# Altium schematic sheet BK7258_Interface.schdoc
size 326 x 187 mm
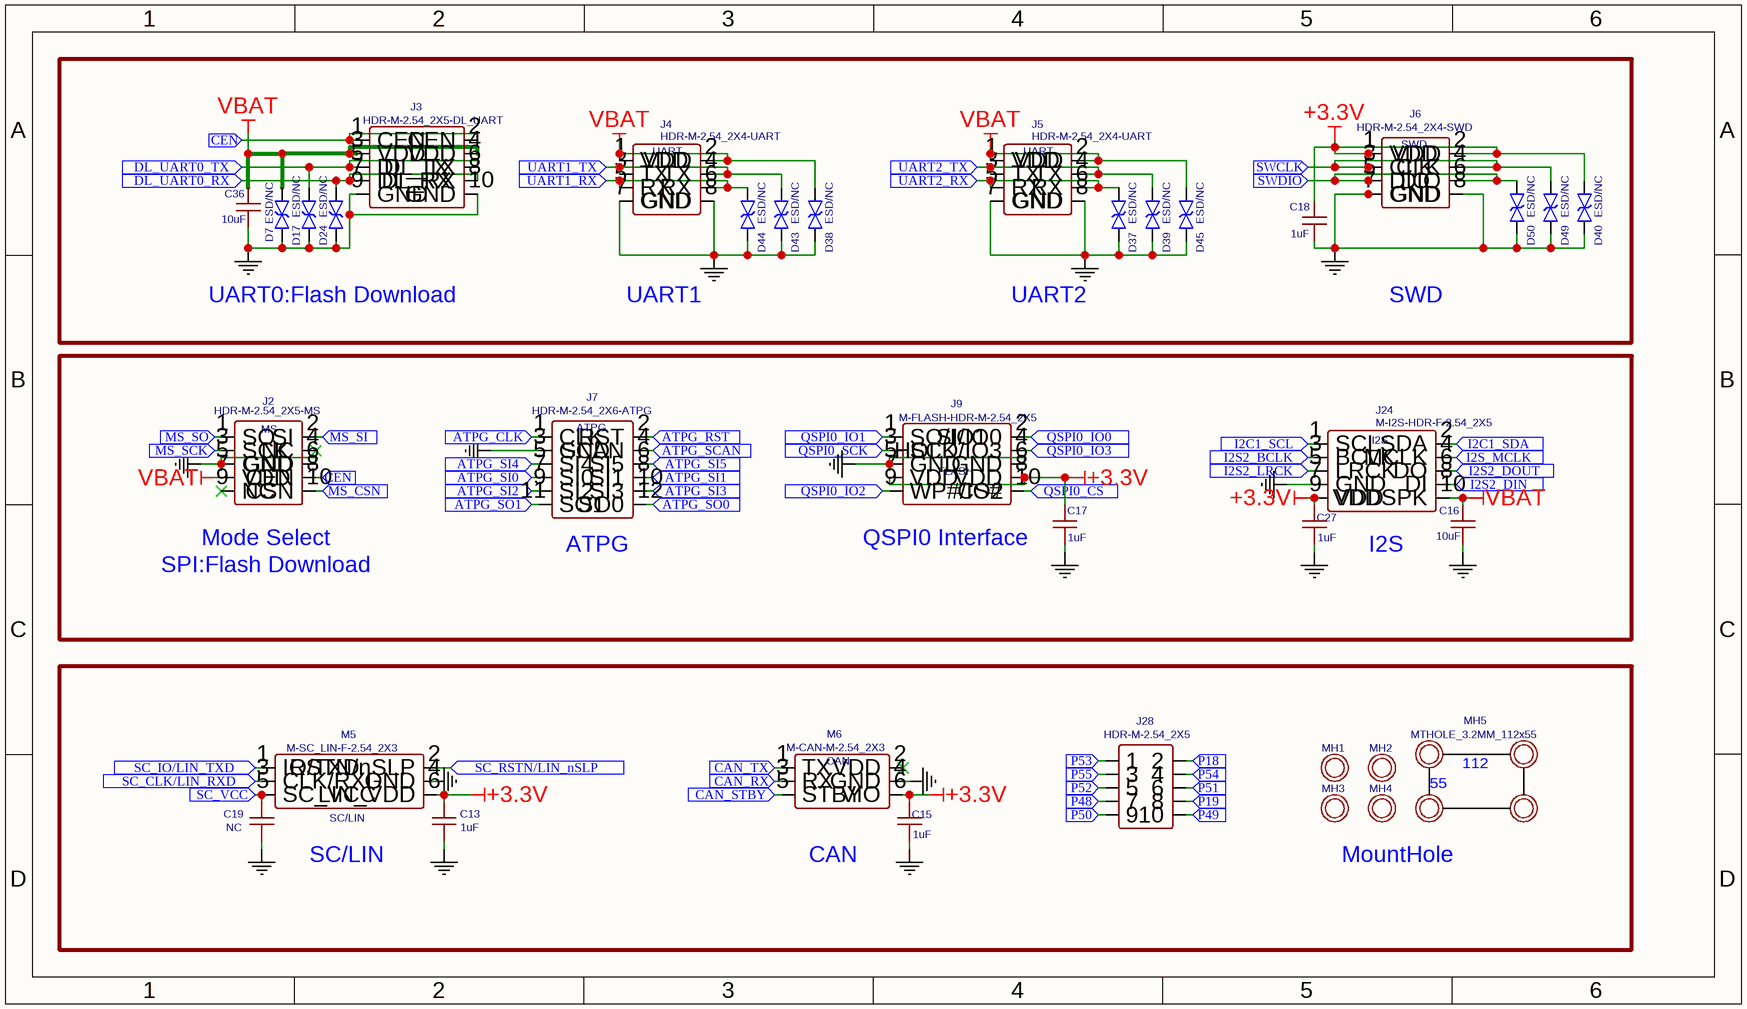
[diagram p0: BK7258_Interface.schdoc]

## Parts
C13  1uF  [C0402]
C15  1uF  [C0402]
C16  10uF  [C0603]
C17  1uF  [C0402]
C18  1uF  [C0402]
C19  NC  [C0402]
C27  1uF  [C0402]
C36  10uF  [C0603]
D7  ESD/NC  [ESD0402]
D17  ESD/NC  [ESD0402]
D24  ESD/NC  [ESD0402]
D37  ESD/NC  [ESD0402]
D38  ESD/NC  [ESD0402]
D39  ESD/NC  [ESD0402]
D40  ESD/NC  [ESD0402]
D43  ESD/NC  [ESD0402]
D44  ESD/NC  [ESD0402]
D45  ESD/NC  [ESD0402]
D49  ESD/NC  [ESD0402]
D50  ESD/NC  [ESD0402]
J2  HDR-M-2.54_2X5-MS  [JH2X5_FLASH]
J3  HDR-M-2.54_2X5-DL_UART  [HDR-M-2.54_2X5-DL_UART]
J4  HDR-M-2.54_2X4-UART  [HDR-M-2.54_2X4-UART]
J5  HDR-M-2.54_2X4-UART  [HDR-M-2.54_2X4-UART]
J6  HDR-M-2.54_2X4-SWD  [HDR-M-2.54_2X4-SWD]
J7  HDR-M-2.54_2X6-ATPG  [JH2X6]
J9  M-FLASH-HDR-M-2.54_2X5  [JH2X5_FLASH]
J24  M-I2S-HDR-F-2.54_2X5  [M-I2S-HDR-F-2.54_2X5]
J28  HDR-M-2.54_2X5  [HDR-M-2.54_2X5]
M5  M-SC_LIN-F-2.54_2X3  [M-SC_LIN-F-2.54_2X3]
M6  M-CAN-M-2.54_2X3  [M-CAN-M-2.54_2X3]
MH1  MTHOLE_3.2MM  [MTHOLE_3.2MM]  (value not drawn)
MH2  MTHOLE_3.2MM  [MTHOLE_3.2MM]  (value not drawn)
MH3  MTHOLE_3.2MM  [MTHOLE_3.2MM]  (value not drawn)
MH4  MTHOLE_3.2MM  [MTHOLE_3.2MM]  (value not drawn)
MH5  MTHOLE_3.2MM_112x55  [MTHOLE_3.2MM_112X55]

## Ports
ATPG_CLK (in), ATPG_RST (in), ATPG_SCAN (in), ATPG_SI0 (in), ATPG_SI1 (in), ATPG_SI2 (in), ATPG_SI3 (in), ATPG_SI4 (in), ATPG_SI5 (in), ATPG_SO0 (in), ATPG_SO1 (in), CAN_RX (in), CAN_STBY (in), CAN_TX (in), CEN (in), DL_UART0_RX (in), DL_UART0_TX (in), I2C1_SCL (in), I2C1_SDA (in), I2S2_BCLK (in), I2S2_DIN (in), I2S2_DOUT (in), I2S2_LRCK (in), I2S_MCLK (in), MS_CSN (in), MS_SCK (in), MS_SI (in), MS_SO (in), P18 (in), P19 (in), P48 (in), P49 (in), P50 (in), P51 (in), P52 (in), P53 (in), P54 (in), P55 (in), QSPI0_CS (in), QSPI0_IO0 (in), QSPI0_IO1 (in), QSPI0_IO2 (in), QSPI0_IO3 (in), QSPI0_SCK (in), SC_CLK/LIN_RXD (in), SC_IO/LIN_TXD (in), SC_RSTN/LIN_nSLP (in), SC_VCC (in), SWCLK (in), SWDIO (in), UART1_RX (in), UART1_TX (in), UART2_RX (in), UART2_TX (in)

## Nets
+3.3V: C13.1 C15.1 C17.1 C18.1 C27.1 D40.1 J6.1(VDD) J6.2(VDD) J9.7(VDD) J9.8(VDD) J24.9(VDD) M5.6(LIN_VDD) M6.6(VIO)
GGND: C13.2 C15.2 C16.2 C17.2 C18.2 C19.2 C27.2 C36.2 D7.2 D17.2 D24.2 D37.2 D38.2 D39.2 D40.2 D43.2 D44.2 D45.2 D49.2 D50.2 J2.5(GND) J2.6(GND) J3.9(GND) J3.10(GND) J4.7(GND) J4.8(GND) J5.7(GND) J5.8(GND) J6.7(GND) J6.8(GND) J7.3(GND) J9.5(GND) J9.6(GND) J24.7(GND) M5.4(GND) M6.4(GND)
VBAT: C16.1 C36.1 D7.1 D38.1 D45.1 J2.7(VDD) J3.3(VDD) J3.4(VDD) J4.1(VDD) J4.2(VDD) J5.1(VDD) J5.2(VDD) J24.10(VDDSPK)
ATPG_CLK: J7.1(CLK) ; port ATPG_CLK
ATPG_RST: J7.2(RST) ; port ATPG_RST
ATPG_SCAN: J7.4(SCAN) ; port ATPG_SCAN
ATPG_SI0: J7.7(SI0) ; port ATPG_SI0
ATPG_SI1: J7.8(SI1) ; port ATPG_SI1
ATPG_SI2: J7.9(SI2) ; port ATPG_SI2
ATPG_SI3: J7.10(SI3) ; port ATPG_SI3
ATPG_SI4: J7.5(SI4) ; port ATPG_SI4
ATPG_SI5: J7.6(SI5) ; port ATPG_SI5
ATPG_SO0: J7.12(SO0) ; port ATPG_SO0
ATPG_SO1: J7.11(SO1) ; port ATPG_SO1
CAN_RX: M6.3(RX) ; port CAN_RX
CAN_STBY: M6.5(STBY) ; port CAN_STBY
CAN_TX: M6.1(TX) ; port CAN_TX
CEN: J2.8(CEN) J3.1(CEN) J3.2(CEN) ; port CEN
DL_UART0_RX: D24.1 J3.7(DL_RX) J3.8(DL_RX) ; port DL_UART0_RX
DL_UART0_TX: D17.1 J3.5(DL_TX) J3.6(DL_TX) ; port DL_UART0_TX
I2C1_SCL: J24.1(SCL) ; port I2C1_SCL
I2C1_SDA: J24.2(SDA) ; port I2C1_SDA
I2S2_BCLK: J24.3(BCLK) ; port I2S2_BCLK
I2S2_DIN: J24.8(DI) ; port I2S2_DIN
I2S2_DOUT: J24.6(DO) ; port I2S2_DOUT
I2S2_LRCK: J24.5(LRCK) ; port I2S2_LRCK
I2S_MCLK: J24.4(MCLK) ; port I2S_MCLK
MS_CSN: J2.10(CSN) ; port MS_CSN
MS_SCK: J2.3(SCK) ; port MS_SCK
MS_SI: J2.2(SI) ; port MS_SI
MS_SO: J2.1(SO) ; port MS_SO
P18: J28.2 ; port P18
P19: J28.8 ; port P19
P48: J28.7 ; port P48
P49: J28.10 ; port P49
P50: J28.9 ; port P50
P51: J28.6 ; port P51
P52: J28.5 ; port P52
P53: J28.1 ; port P53
P54: J28.4 ; port P54
P55: J28.3 ; port P55
QSPI0_CS: J9.10(CS#) ; port QSPI0_CS
QSPI0_IO0: J9.2(SI/IO0) ; port QSPI0_IO0
QSPI0_IO1: J9.1(SO/IO1) ; port QSPI0_IO1
QSPI0_IO2: J9.9(WP#/IO2) ; port QSPI0_IO2
QSPI0_IO3: J9.4(HOLD/IO3) ; port QSPI0_IO3
QSPI0_SCK: J9.3(SCK) ; port QSPI0_SCK
SC_CLK/LIN_RXD: M5.3(CLK/RXD) ; port SC_CLK/LIN_RXD
SC_IO/LIN_TXD: M5.1(IO/TXD) ; port SC_IO/LIN_TXD
SC_RSTN/LIN_nSLP: M5.2(RSTN/nSLP) ; port SC_RSTN/LIN_nSLP
SC_VCC: C19.1 M5.5(SC_VCC) ; port SC_VCC
SWCLK: D49.1 J6.3(CLK) J6.4(CLK) ; port SWCLK
SWDIO: D50.1 J6.5(DIO) J6.6(DIO) ; port SWDIO
UART1_RX: D44.1 J4.5(RX) J4.6(RX) ; port UART1_RX
UART1_TX: D43.1 J4.3(TX) J4.4(TX) ; port UART1_TX
UART2_RX: D37.1 J5.5(RX) J5.6(RX) ; port UART2_RX
UART2_TX: D39.1 J5.3(TX) J5.4(TX) ; port UART2_TX

Not connected (* = marked no-connect by the designer): J2 4(NC)* 9(NC)*; M6 2(VDD)*

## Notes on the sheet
- UART0:Flash Download
- UART1
- UART2
- SWD
- (near J2) Mode Select
- (near J7) ATPG
- QSPI0 Interface
- I2S
- SPI:Flash Download
- SC/LIN
- CAN
- MountHole

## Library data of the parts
C13 C15 C17 C18 C27 = 1uF: Manufacturer Part Number: 08055A390JATMA; Manufacturer: AVX; APN: C012-0
C16 C36 = 10uF: Manufacturer Part Number: 06035A101KAT2A; Manufacturer: AVX; APN: C029-0
C19 = NC: Manufacturer Part Number: 08055A390JATMA; Manufacturer: AVX; APN: C012-0
D7 D17 D24 D37-D40 D43-D45 D49 D50 = ESD/NC: Contributor: D-MAN
J2 = HDR-M-2.54_2X5-MS: Contributor: qunshan.xu
J3 = HDR-M-2.54_2X5-DL_UART: Contributor: qunshan.xu
J4 J5 = HDR-M-2.54_2X4-UART: Contributor: qunshan.xu
J6 = HDR-M-2.54_2X4-SWD: Contributor: qunshan.xu
J7 = HDR-M-2.54_2X6-ATPG: Contributor: qunshan.xu
J9 = M-FLASH-HDR-M-2.54_2X5: Contributor: qunshan.xu
J24 = M-I2S-HDR-F-2.54_2X5: Contributor: qunshan.xu
J28 = HDR-M-2.54_2X5: Contributor: LCEDA_Lib
M5 = M-SC_LIN-F-2.54_2X3: Contributor: qunshan.xu
M6 = M-CAN-M-2.54_2X3: Contributor: qunshan.xu
MH1-MH4 = MTHOLE_3.2MM: Contributor: qunshan.xu
MH5 = MTHOLE_3.2MM_112x55: Contributor: qunshan.xu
